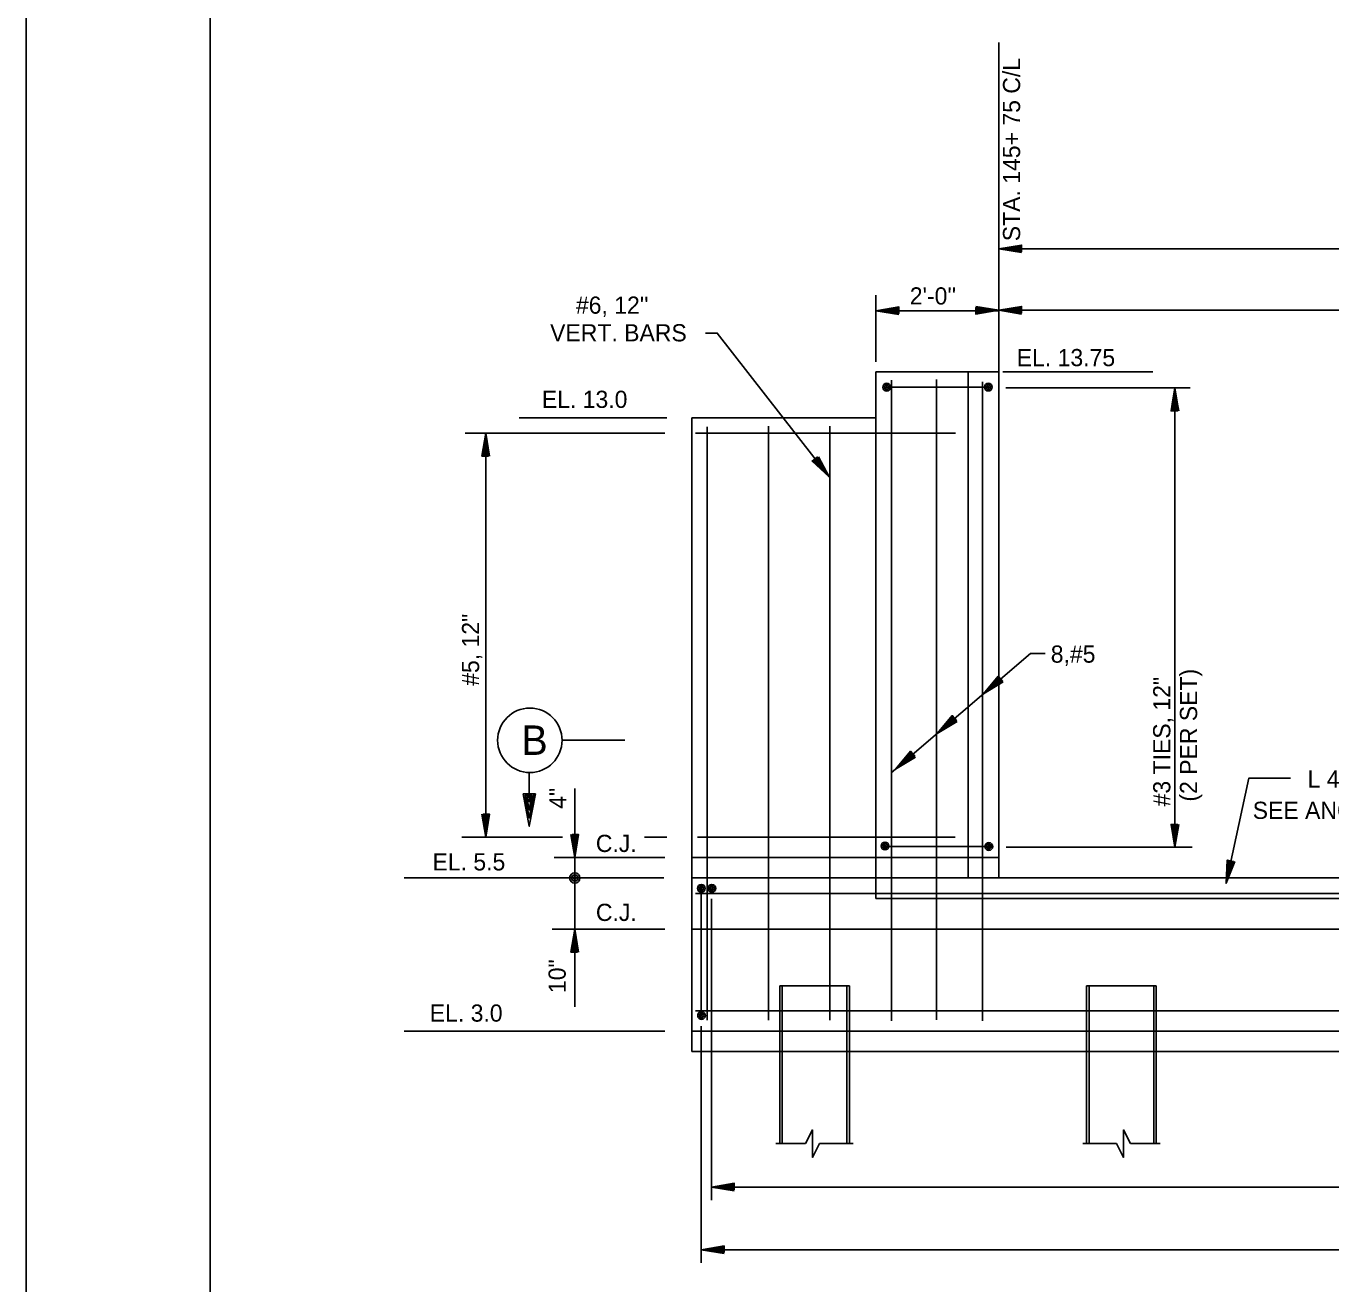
# Model space of a CAD drawing. Extents: x -11983 to -11903, y -13969.5 to -13913.5.
# Drawn here: x -11983.01 to -11961.75, y -13955.79 to -13935.3 of the extents above; entities that cross this region are included whole.
import ezdxf

# ---------------------------------------------------------------- set-up
doc = ezdxf.new("R2010")
doc.units = 0
for name, color, linetype in [('Level 1', 7, 'Continuous'), ('Level 13', 7, 'Continuous'), ('Level 2', 7, 'Continuous'), ('Level 22', 7, 'Continuous'), ('Level 3', 7, 'Continuous'), ('Level 50', 7, 'Continuous'), ('Level 6', 7, 'Continuous')]:
    doc.layers.add(name, color=color, linetype=linetype)

msp = doc.modelspace()

# ---------------------------------------------------------------- linework, layer by layer
at = {"layer": 'Level 1'}
for points in [[(-11983.012, -13913.481), (-11903.012, -13913.481), (-11903.012, -13969.481), (-11983.012, -13969.481)], [(-11980.012, -13914.481), (-11904.012, -13914.481), (-11904.012, -13968.481), (-11980.012, -13968.481)]]:
    msp.add_lwpolyline(points, close=True, dxfattribs=at)
at = {"layer": 'Level 13'}
for points in [[(-11970.31, -13953.508), (-11970.198, -13953.283), (-11970.198, -13953.732), (-11970.085, -13953.508)], [(-11965.017, -13953.508), (-11965.129, -13953.283), (-11965.129, -13953.732), (-11965.241, -13953.508)]]:
    msp.add_lwpolyline(points, dxfattribs=at)
at = {"layer": 'Level 2'}
for p, q in [((-11969.163, -13949.179), (-11969.163, -13940.928)), ((-11969.163, -13940.929), (-11967.163, -13940.929)), ((-11969.163, -13940.93), (-11969.163, -13940.93)), ((-11968.912, -13941.458), (-11968.912, -13941.065)), ((-11967.663, -13941.458), (-11967.663, -13940.928)), ((-11967.163, -13941.458), (-11967.163, -13940.928)), ((-11969.163, -13941.679), (-11969.163, -13941.459)), ((-11968.912, -13942.322), (-11968.912, -13941.459)), ((-11967.663, -13942.322), (-11967.663, -13941.459)), ((-11967.163, -13942.322), (-11967.163, -13941.459)), ((-11972.163, -13941.679), (-11969.163, -13941.679)), ((-11969.163, -13942.322), (-11969.163, -13941.679)), ((-11968.912, -13951.504), (-11968.912, -13942.322)), ((-11967.663, -13949.179), (-11967.663, -13942.322)), ((-11967.163, -13949.179), (-11967.163, -13942.322)), ((-11972.163, -13948.846), (-11967.163, -13948.846)), ((-11972.163, -13952.009), (-11972.163, -13949.179)), ((-11972.163, -13952.009), (-11972.163, -13949.179)), ((-11972.163, -13949.179), (-11955.163, -13949.179)), ((-11969.163, -13949.179), (-11969.163, -13949.512)), ((-11969.163, -13949.512), (-11955.163, -13949.512)), ((-11972.163, -13950.011), (-11955.163, -13950.011)), ((-11970.731, -13950.937), (-11969.596, -13950.937)), ((-11970.731, -13950.937), (-11970.731, -13952.009)), ((-11970.69, -13950.937), (-11970.69, -13952.009)), ((-11969.637, -13950.937), (-11969.637, -13952.009)), ((-11969.596, -13950.937), (-11969.596, -13952.009)), ((-11964.596, -13950.937), (-11965.731, -13950.937)), ((-11965.731, -13950.937), (-11965.731, -13952.009)), ((-11965.69, -13950.937), (-11965.69, -13952.009)), ((-11964.637, -13950.937), (-11964.637, -13952.009)), ((-11964.596, -13950.937), (-11964.596, -13952.009)), ((-11972.163, -13951.676), (-11955.163, -13951.676)), ((-11971.059, -13951.676), (-11969.074, -13951.676)), ((-11966.078, -13951.676), (-11965.163, -13951.676)), ((-11964.2, -13951.676), (-11966.078, -13951.676)), ((-11964.2, -13951.676), (-11966.078, -13951.676)), ((-11964.2, -13951.676), (-11966.078, -13951.676)), ((-11964.268, -13951.676), (-11966.078, -13951.676)), ((-11964.2, -13951.676), (-11965.163, -13951.676)), ((-11972.163, -13952.009), (-11955.163, -13952.009)), ((-11971.059, -13952.009), (-11969.074, -13952.009)), ((-11970.731, -13953.508), (-11970.731, -13952.009)), ((-11970.69, -13953.508), (-11970.69, -13952.009)), ((-11969.637, -13953.508), (-11969.637, -13952.009)), ((-11969.596, -13953.508), (-11969.596, -13952.009)), ((-11966.078, -13952.009), (-11965.163, -13952.009)), ((-11964.2, -13952.009), (-11966.078, -13952.009)), ((-11964.2, -13952.009), (-11966.078, -13952.009)), ((-11964.2, -13952.009), (-11966.078, -13952.009)), ((-11964.268, -13952.009), (-11966.078, -13952.009)), ((-11965.731, -13953.508), (-11965.731, -13952.009)), ((-11965.69, -13953.508), (-11965.69, -13952.009)), ((-11964.2, -13952.009), (-11965.163, -13952.009)), ((-11964.637, -13953.508), (-11964.637, -13952.009)), ((-11964.596, -13953.508), (-11964.596, -13952.009)), ((-11970.794, -13953.508), (-11970.31, -13953.508)), ((-11970.085, -13953.508), (-11969.533, -13953.508)), ((-11965.241, -13953.508), (-11965.793, -13953.508)), ((-11964.532, -13953.508), (-11965.017, -13953.508))]:
    msp.add_line(p, q, dxfattribs=at)
at = {"layer": 'Level 22'}
for p, q in [((-11967.163, -13939.926), (-11963.329, -13939.926)), ((-11963.329, -13939.927), (-11955.163, -13939.927)), ((-11967.425, -13941.091), (-11967.425, -13941.458)), ((-11967.425, -13941.459), (-11967.425, -13942.322)), ((-11967.425, -13942.322), (-11967.425, -13951.504))]:
    msp.add_line(p, q, dxfattribs=at)
at = {"layer": 'Level 3'}
for p, q in [((-11967.163, -13940.743), (-11967.163, -13935.564)), ((-11967.163, -13941.458), (-11967.163, -13938.651)), ((-11963.329, -13938.926), (-11967.163, -13938.926)), ((-11955.163, -13938.927), (-11963.329, -13938.927)), ((-11969.163, -13940.768), (-11969.163, -13939.683)), ((-11969.163, -13939.934), (-11967.163, -13939.934)), ((-11967.267, -13939.928), (-11967.267, -13939.928)), ((-11967.163, -13939.928), (-11967.163, -13939.928)), ((-11967.094, -13940.928), (-11964.652, -13940.928)), ((-11967.049, -13941.191), (-11964.045, -13941.191)), ((-11964.292, -13941.458), (-11964.292, -13941.191)), ((-11967.163, -13941.579), (-11967.163, -13941.459)), ((-11964.292, -13942.322), (-11964.292, -13941.459)), ((-11974.975, -13941.679), (-11972.571, -13941.679)), ((-11972.163, -13942.322), (-11972.163, -13941.679)), ((-11975.858, -13941.929), (-11972.602, -13941.929)), ((-11975.522, -13948.513), (-11975.522, -13941.929)), ((-11972.163, -13949.179), (-11972.163, -13942.322)), ((-11964.292, -13948.679), (-11964.292, -13942.322)), ((-11973.257, -13946.935), (-11974.289, -13946.935)), ((-11974.813, -13947.81), (-11974.813, -13947.46)), ((-11968.843, -13947.404), (-11968.843, -13947.404)), ((-11968.764, -13947.336), (-11968.764, -13947.336)), ((-11974.071, -13948.846), (-11974.071, -13947.721)), ((-11975.911, -13948.513), (-11974.272, -13948.513)), ((-11972.935, -13948.513), (-11972.569, -13948.513)), ((-11967.044, -13948.679), (-11964.009, -13948.679)), ((-11964.292, -13948.575), (-11964.292, -13948.575)), ((-11964.292, -13948.679), (-11964.292, -13948.679)), ((-11974.407, -13948.846), (-11972.602, -13948.846)), ((-11974.071, -13949.179), (-11974.071, -13948.846)), ((-11976.849, -13949.179), (-11972.619, -13949.179)), ((-11974.071, -13950.011), (-11974.071, -13949.179)), ((-11971.846, -13949.52), (-11971.846, -13954.431)), ((-11974.442, -13950.011), (-11972.602, -13950.011)), ((-11974.071, -13951.279), (-11974.071, -13950.011)), ((-11976.849, -13951.676), (-11972.602, -13951.676)), ((-11972.013, -13951.593), (-11972.013, -13955.452)), ((-11971.846, -13954.215), (-11954.173, -13954.215)), ((-11972.013, -13955.238), (-11954.173, -13955.238))]:
    msp.add_line(p, q, dxfattribs=at)
for points in [[(-11967.537, -13939.866), (-11967.163, -13939.928), (-11967.537, -13939.99), (-11967.537, -13939.884), (-11967.267, -13939.928), (-11967.521, -13939.97), (-11967.521, -13939.902), (-11967.367, -13939.928), (-11967.505, -13939.95), (-11967.505, -13939.922), (-11967.471, -13939.928)], [(-11971.941, -13940.298), (-11971.75, -13940.298), (-11969.926, -13942.641)], [(-11970.102, -13942.317), (-11969.926, -13942.641), (-11970.205, -13942.384), (-11970.121, -13942.319), (-11969.99, -13942.559), (-11970.179, -13942.384), (-11970.126, -13942.342), (-11970.052, -13942.48), (-11970.154, -13942.384), (-11970.132, -13942.367), (-11970.116, -13942.398)], [(-11966.406, -13945.519), (-11966.643, -13945.519), (-11968.913, -13947.464)], [(-11968.519, -13947.208), (-11968.843, -13947.404), (-11968.599, -13947.114), (-11968.53, -13947.194), (-11968.764, -13947.336), (-11968.599, -13947.139), (-11968.554, -13947.191), (-11968.688, -13947.271), (-11968.598, -13947.165), (-11968.579, -13947.186), (-11968.609, -13947.204)], [(-11962.407, -13947.553), (-11963.088, -13947.553), (-11963.458, -13949.265)], [(-11974.74, -13947.81), (-11974.714, -13947.81), (-11974.813, -13948.335), (-11974.911, -13947.81), (-11974.74, -13947.81), (-11974.812, -13948.201), (-11974.882, -13947.835), (-11974.769, -13947.835), (-11974.812, -13948.069), (-11974.851, -13947.86), (-11974.798, -13947.86), (-11974.812, -13947.935), (-11974.821, -13947.885)], [(-11964.23, -13948.305), (-11964.292, -13948.679), (-11964.354, -13948.305), (-11964.248, -13948.305), (-11964.292, -13948.575), (-11964.334, -13948.321), (-11964.266, -13948.321), (-11964.292, -13948.475), (-11964.314, -13948.337), (-11964.286, -13948.337), (-11964.292, -13948.371)]]:
    msp.add_lwpolyline(points, dxfattribs=at)
msp.add_circle((-11974.803, -13946.935), 0.525, dxfattribs=at)
at = {"layer": 'Level 50'}
for p, q in [((-11967.163, -13938.926), (-11967.163, -13938.926)), ((-11967.059, -13938.926), (-11967.059, -13938.926)), ((-11969.163, -13939.934), (-11969.163, -13939.934)), ((-11969.059, -13939.934), (-11969.059, -13939.934)), ((-11967.163, -13939.926), (-11967.163, -13939.926)), ((-11967.059, -13939.926), (-11967.059, -13939.926)), ((-11964.292, -13941.191), (-11964.292, -13941.191)), ((-11964.292, -13941.295), (-11964.292, -13941.295)), ((-11975.522, -13941.929), (-11975.522, -13941.929)), ((-11975.522, -13942.033), (-11975.522, -13942.033)), ((-11967.413, -13946.179), (-11967.413, -13946.179)), ((-11967.334, -13946.111), (-11967.334, -13946.111)), ((-11968.165, -13946.823), (-11968.165, -13946.823)), ((-11968.086, -13946.755), (-11968.086, -13946.755)), ((-11975.522, -13948.409), (-11975.522, -13948.409)), ((-11975.522, -13948.513), (-11975.522, -13948.513)), ((-11974.071, -13948.742), (-11974.071, -13948.742)), ((-11974.071, -13948.846), (-11974.071, -13948.846)), ((-11963.436, -13949.163), (-11963.436, -13949.163)), ((-11963.458, -13949.265), (-11963.458, -13949.265)), ((-11974.071, -13950.011), (-11974.071, -13950.011)), ((-11974.071, -13950.115), (-11974.071, -13950.115)), ((-11971.846, -13954.215), (-11971.846, -13954.215)), ((-11971.742, -13954.215), (-11971.742, -13954.215)), ((-11972.013, -13955.238), (-11972.013, -13955.238)), ((-11971.909, -13955.238), (-11971.909, -13955.238))]:
    msp.add_line(p, q, dxfattribs=at)
for points in [[(-11966.789, -13938.988), (-11967.163, -13938.926), (-11966.789, -13938.864), (-11966.789, -13938.97), (-11967.059, -13938.926), (-11966.805, -13938.884), (-11966.805, -13938.952), (-11966.959, -13938.926), (-11966.821, -13938.904), (-11966.821, -13938.932), (-11966.855, -13938.926)], [(-11968.789, -13939.996), (-11969.163, -13939.934), (-11968.789, -13939.872), (-11968.789, -13939.978), (-11969.059, -13939.934), (-11968.805, -13939.892), (-11968.805, -13939.96), (-11968.959, -13939.934), (-11968.821, -13939.912), (-11968.821, -13939.94), (-11968.855, -13939.934)], [(-11966.789, -13939.988), (-11967.163, -13939.926), (-11966.789, -13939.864), (-11966.789, -13939.97), (-11967.059, -13939.926), (-11966.805, -13939.884), (-11966.805, -13939.952), (-11966.959, -13939.926), (-11966.821, -13939.904), (-11966.821, -13939.932), (-11966.855, -13939.926)], [(-11964.248, -13941.458), (-11964.292, -13941.191), (-11964.336, -13941.458)], [(-11964.266, -13941.458), (-11964.292, -13941.295), (-11964.319, -13941.458)], [(-11964.336, -13941.459), (-11964.354, -13941.567), (-11964.248, -13941.567), (-11964.266, -13941.459)], [(-11964.319, -13941.459), (-11964.334, -13941.551), (-11964.266, -13941.551), (-11964.281, -13941.459)], [(-11964.302, -13941.459), (-11964.314, -13941.535), (-11964.286, -13941.535), (-11964.292, -13941.501)], [(-11964.281, -13941.458), (-11964.292, -13941.395), (-11964.302, -13941.458)], [(-11964.23, -13941.567), (-11964.248, -13941.459)], [(-11975.46, -13942.303), (-11975.522, -13941.929), (-11975.584, -13942.303), (-11975.478, -13942.303), (-11975.522, -13942.033), (-11975.564, -13942.287), (-11975.496, -13942.287), (-11975.522, -13942.133), (-11975.544, -13942.271), (-11975.516, -13942.271), (-11975.522, -13942.237)], [(-11967.089, -13945.983), (-11967.413, -13946.179), (-11967.17, -13945.889), (-11967.101, -13945.969), (-11967.334, -13946.111), (-11967.169, -13945.914), (-11967.124, -13945.966), (-11967.258, -13946.046), (-11967.168, -13945.94), (-11967.15, -13945.961), (-11967.179, -13945.979)], [(-11967.84, -13946.627), (-11968.165, -13946.823), (-11967.921, -13946.532), (-11967.852, -13946.613), (-11968.086, -13946.755), (-11967.92, -13946.558), (-11967.876, -13946.61), (-11968.01, -13946.69), (-11967.919, -13946.584), (-11967.901, -13946.605), (-11967.931, -13946.622)], [(-11975.584, -13948.139), (-11975.522, -13948.513), (-11975.46, -13948.139), (-11975.566, -13948.139), (-11975.522, -13948.409), (-11975.48, -13948.155), (-11975.548, -13948.155), (-11975.522, -13948.309), (-11975.5, -13948.171), (-11975.528, -13948.171), (-11975.522, -13948.205)], [(-11974.133, -13948.472), (-11974.071, -13948.846), (-11974.009, -13948.472), (-11974.115, -13948.472), (-11974.071, -13948.742), (-11974.029, -13948.488), (-11974.097, -13948.488), (-11974.071, -13948.642), (-11974.049, -13948.504), (-11974.077, -13948.504), (-11974.071, -13948.538)], [(-11963.318, -13948.912), (-11963.458, -13949.265), (-11963.439, -13948.886), (-11963.336, -13948.909), (-11963.436, -13949.163), (-11963.423, -13948.906), (-11963.357, -13948.92), (-11963.415, -13949.065), (-11963.407, -13948.926), (-11963.38, -13948.932), (-11963.393, -13948.964)], [(-11974.009, -13950.385), (-11974.071, -13950.011), (-11974.133, -13950.385), (-11974.027, -13950.385), (-11974.071, -13950.115), (-11974.113, -13950.369), (-11974.045, -13950.369), (-11974.071, -13950.215), (-11974.093, -13950.353), (-11974.065, -13950.353), (-11974.071, -13950.319)], [(-11971.472, -13954.277), (-11971.846, -13954.215), (-11971.472, -13954.153), (-11971.472, -13954.259), (-11971.742, -13954.215), (-11971.488, -13954.173), (-11971.488, -13954.241), (-11971.642, -13954.215), (-11971.504, -13954.193), (-11971.504, -13954.221), (-11971.538, -13954.215)], [(-11971.639, -13955.3), (-11972.013, -13955.238), (-11971.639, -13955.176), (-11971.639, -13955.282), (-11971.909, -13955.238), (-11971.655, -13955.196), (-11971.655, -13955.264), (-11971.809, -13955.238), (-11971.671, -13955.216), (-11971.671, -13955.244), (-11971.705, -13955.238)]]:
    msp.add_lwpolyline(points, dxfattribs=at)
for radius in [0.0844, 0.0527, 0.0211]:
    msp.add_circle((-11974.071, -13949.179), radius, dxfattribs=at)
at = {"layer": 'Level 6'}
for p, q in [((-11968.179, -13941.458), (-11968.179, -13941.053)), ((-11968.985, -13941.178), (-11967.293, -13941.178)), ((-11968.179, -13942.322), (-11968.179, -13941.459)), ((-11972.103, -13941.929), (-11967.866, -13941.929)), ((-11971.913, -13942.322), (-11971.913, -13941.829)), ((-11970.913, -13942.322), (-11970.913, -13941.816)), ((-11969.913, -13942.322), (-11969.913, -13941.816)), ((-11971.913, -13951.495), (-11971.913, -13942.322)), ((-11970.913, -13951.495), (-11970.913, -13942.322)), ((-11969.913, -13951.495), (-11969.913, -13942.322)), ((-11968.179, -13951.489), (-11968.179, -13942.322)), ((-11972.071, -13948.513), (-11967.873, -13948.513)), ((-11968.997, -13948.664), (-11967.293, -13948.664)), ((-11972.013, -13951.42), (-11972.013, -13949.329)), ((-11972.103, -13949.429), (-11955.163, -13949.429)), ((-11972.103, -13951.343), (-11955.163, -13951.343)), ((-11966.078, -13951.343), (-11965.163, -13951.343)), ((-11964.2, -13951.343), (-11966.078, -13951.343)), ((-11964.2, -13951.343), (-11966.078, -13951.343)), ((-11964.2, -13951.343), (-11966.078, -13951.343)), ((-11964.2, -13951.343), (-11965.163, -13951.343))]:
    msp.add_line(p, q, dxfattribs=at)
for centre, radius in [((-11968.989, -13941.181), 0.0633), ((-11968.989, -13941.181), 0.0396), ((-11968.989, -13941.181), 0.0158), ((-11967.332, -13941.179), 0.0633), ((-11967.332, -13941.179), 0.0396), ((-11967.332, -13941.179), 0.0158), ((-11969.016, -13948.658), 0.0633), ((-11969.016, -13948.658), 0.0396), ((-11969.016, -13948.658), 0.0158), ((-11967.323, -13948.666), 0.0633), ((-11967.323, -13948.666), 0.0396), ((-11967.323, -13948.666), 0.0158), ((-11972.01, -13949.348), 0.0633), ((-11972.01, -13949.348), 0.0396), ((-11972.01, -13949.348), 0.0158), ((-11971.838, -13949.348), 0.0633), ((-11971.838, -13949.348), 0.0396), ((-11971.838, -13949.348), 0.0158), ((-11972.005, -13951.421), 0.0633), ((-11972.005, -13951.421), 0.0396), ((-11972.005, -13951.421), 0.0158)]:
    msp.add_circle(centre, radius, dxfattribs=at)

# ---------------------------------------------------------------- texts
at = {"layer": 'Level 2'}
msp.add_text('B', height=0.48, dxfattribs=at).set_placement((-11974.941, -13947.173))
at = {"layer": 'Level 3'}
for s, p in [('STA. 145+ 75 C/L', (-11966.814, -13938.802)), ('#5, 12"', (-11975.63, -13946.047)), ('#3 TIES, 12"', (-11964.366, -13948.012)), ('(2 PER SET)', (-11963.93, -13947.934)), ('4"', (-11974.207, -13948.051)), ('10"', (-11974.219, -13951.054))]:
    msp.add_text(s, height=0.28, rotation=90, dxfattribs=at).set_placement(p)
for s, p in [("2'-0''", (-11968.612, -13939.833)), ("#6, 12''", (-11974.053, -13939.983)), ('VERT. BARS', (-11974.473, -13940.434)), ('EL. 13.75', (-11966.869, -13940.838)), ('EL. 13.0', (-11974.608, -13941.518)), ('8,#5 ', (-11966.315, -13945.67)), ('L 4 X 4 X … X 32\'-0"', (-11962.13, -13947.707)), ('SEE ANGLE DETAIL ON DWG. 46', (-11963.024, -13948.216)), ('C.J.', (-11973.728, -13948.755)), ('EL. 5.5', (-11976.39, -13949.056)), ('C.J.', (-11973.727, -13949.879)), ('EL. 3.0', (-11976.434, -13951.52))]:
    msp.add_text(s, height=0.28, dxfattribs=at).set_placement(p)

doc.saveas('drawing.dxf')
